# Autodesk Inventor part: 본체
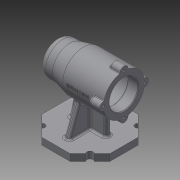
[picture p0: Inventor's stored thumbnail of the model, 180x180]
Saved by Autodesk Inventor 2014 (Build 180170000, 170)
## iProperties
Created: 2021-01
Part Number: 본체
Material: Generic
Document SubType Name: Modeling
Designer: kh
Density: 1 g/cm^3
Appearance: Default
Author: kh
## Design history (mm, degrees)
sketch "Sketch1" dims "d0" = 100
  geometry: L1 (20.711, 50)-(50, 20.711); L2 (50, 20.711)-(50, -20.711); L3 (50, -20.711)-(20.711, -50); L4 (20.711, -50)-(-20.711, -50); L5 (-20.711, -50)-(-50, -20.711); L6 (-50, -20.711)-(-50, 20.711); L7 (-50, 20.711)-(-20.711, 50); L8 (-20.711, 50)-(20.711, 50); L9 (0, 0)-(0, 50); 4 further points
  constraints: 18 end point, 3 coincident, 1 midpoint, 1 vertical, 20 other
  dimensions: "d12" = 50 distance of L9.start L9.end
extrude "Extrusion1" new body sketch "Sketch1" distance "d1" = 10; taper "d2" = 0 deg
workplane "Work Plane1"
sketch "Sketch2"
  geometry: L1 (-19.134, 0)-(19.134, 0) reference; L2 (-19.134, 0)-(-19.134, 10) reference; L3 (19.134, 10)-(-19.134, 10) reference; L4 (19.134, 0)-(19.134, 10) reference; L5 (-46.194, 0)-(-19.134, 0) reference; L6 (-46.194, 0)-(-46.194, 10) reference; L7 (-19.134, 10)-(-46.194, 10) reference; L8 (-19.134, 0)-(-19.134, 10) reference; L9 (19.134, 0)-(46.194, 0) reference; L10 (19.134, 0)-(19.134, 10) reference; L11 (46.194, 10)-(19.134, 10) reference; L12 (46.194, 0)-(46.194, 10) reference; L13 (-50, 75)-(-30, 75); L14 (-30, 75)-(-30, 100); L15 (-30, 100)-(-50, 100); L16 (-50, 100)-(-50, 75); L17 (-30, 75)-(-10, 75); L18 (-10, 75)-(-10, 105); L19 (-30, 100)-(-30, 75); L20 (-10, 75)-(50, 75); L21 (50, 75)-(50, 105); L22 (50, 105)-(-10, 105); L23 (-10, 105)-(-10, 75); L24 (-30, 100)-(-10, 105); L25 (-50, 0)-(-20.711, 0) reference; L26 (-50, 0)-(-50, 10) reference; L27 (-20.711, 10)-(-50, 10) reference; L28 (-20.711, 0)-(-20.711, 10) reference; L29 (-20.711, 0)-(20.711, 0) reference; L30 (-20.711, 0)-(-20.711, 10) reference; L31 (20.711, 10)-(-20.711, 10) reference; L32 (20.711, 0)-(20.711, 10) reference; L33 (20.711, 0)-(50, 0) reference; L34 (20.711, 0)-(20.711, 10) reference; L35 (50, 10)-(20.711, 10) reference; L36 (50, 0)-(50, 10) reference
  constraints: 24 end point, 5 parallel, 3 horizontal, 3 perpendicular, 1 collinear
  dimensions: "d5" = 50 diameter of L15 L13; "d7" = 60 diameter of L22 L20; "d8" = 100 distance between parallel lines of L21 L16; "d9" = 40 distance between parallel lines of L16 L18; "d10" = 20 distance between parallel lines of L16 L14; "d14" = 75 distance of L13.start L25.start
revolve "Revolution2" sketch "Sketch2" stored, may be unused: angle "d15" = 90 deg
workplane "Work Plane2"
sketch "Sketch3"
  geometry: L1 (-50, 50)-(-50, 100) reference; L2 (50, 45)-(50, 105) reference; L3 (-50, 75)-(50, 75); L4 (50, 75)-(35, 75); L5 (35, 75)-(35, 96); L6 (35, 96)-(50, 96); L7 (50, 96)-(50, 75); L8 (35, 75)-(-7, 75); L9 (-7, 75)-(-7, 99); L10 (-7, 99)-(35, 99); L11 (35, 99)-(35, 75); L12 (-7, 75)-(-19, 75); L13 (-19, 75)-(-19, 96); L14 (-19, 96)-(-7, 96); L15 (-7, 96)-(-7, 75); L16 (-19, 75)-(-37, 75); L17 (-37, 75)-(-37, 92.5); L18 (-37, 92.5)-(-19, 92.5); L19 (-19, 92.5)-(-19, 75); L20 (-37, 75)-(-41, 75); L21 (-41, 75)-(-41, 91); L22 (-41, 91)-(-37, 91); L23 (-37, 91)-(-37, 75); L24 (-41, 75)-(-44, 75); L25 (-44, 75)-(-44, 85.5); L26 (-44, 85.5)-(-41, 85.5); L27 (-41, 85.5)-(-41, 75); 1 further point
  constraints: 50 end point, 12 parallel, 6 horizontal, 6 perpendicular, 2 midpoint
  dimensions: "d17" = 15 distance between parallel lines of L5 L7; "d18" = 42 distance between parallel lines of L15 L5; "d19" = 12 distance between parallel lines of L13 L15; "d20" = 18 distance between parallel lines of L17 L13; "d21" = 4 distance between parallel lines of L17 L21; "d22" = 3 distance between parallel lines of L21 L25; "d23" = 42 diameter of L6 L3; "d24" = 48 diameter of L10 L3; "d25" = 42 diameter of L14 L12; "d26" = 35 diameter of L18 L16; "d27" = 32 diameter of L22 L3; "d28" = 21 diameter of L26 L24
revolve "Revolution3" sketch "Sketch3" stored, may be unused: angle "d29" = 90 deg
fillet "Fillet1" dims "d30" = 0.3
fillet "Fillet2" dims "d31" = 3
fillet "Fillet3" dims "d32" = 3
chamfer "Chamfer1" distance "d33" = 1; stored, may be unused: second distance "d34" = 2, angle "d35" = 45 deg
sketch "Sketch4" dims "d36" = 60
  geometry: L1 (0, 0)-(0, -34.728); C1 r 25 at (0, 0) reference; C2 r 30 at (0, 0) reference; C3 r 6 at (0, -30); 2 further points
  constraints: 2 coincident, 2 end point, 1 centre point, 1 point on line, 1 vertical, 1 vertical alignment, 2 other
  dimensions: "d37" = 12 diameter of C3
extrude "Extrusion2" join sketch "Sketch4" distance "d38" = 16; taper "d39" = 0 deg
pattern_circular "Circular Pattern1" dims angle "d41" = 360 deg
sketch "Sketch5"
  geometry: C1 r 22 at (0, 30) reference; A1 r 30 centre (0, 30) between (-29.4, 24.03) and (-5.97, 0.6) reference; A2 r 6 centre (0, 0) between (-5.97, 0.6) and (5.97, 0.6) reference; A3 r 30 centre (0, 30) between (5.97, 0.6) and (29.4, 24.03) reference; A4 r 6 centre (30, 30) between (29.4, 24.03) and (29.4, 35.97) reference; A5 r 30 centre (0, 30) between (29.4, 35.97) and (5.97, 59.4) reference; A6 r 6 centre (0, 60) between (5.97, 59.4) and (-5.97, 59.4) reference; A7 r 30 centre (0, 30) between (-5.97, 59.4) and (-29.4, 35.97) reference; A8 r 6 centre (-30, 30) between (-29.4, 35.97) and (-29.4, 24.03) reference; 5 further points
  constraints: 4 coincident
hole "Hole1" sketch "Sketch5" at (0, 0), (30, 30), (0, 60), (-30, 30) diameter "d43" = 3.242; stored, may be unused: countersink angle "d47" = 90 deg, drill point angle "d49" = 118 deg; dims "d44" = 8, "d45" = 4, "d46" = 2, "d48" = 10
sketch "Sketch6"
  geometry: L1 (20.711, 50)-(50, 20.711) reference; L2 (50, 20.711)-(50, -20.711) reference; L3 (50, -20.711)-(20.711, -50) reference; L4 (20.711, -50)-(-20.711, -50) reference; L5 (-20.711, -50)-(-50, -20.711) reference; L6 (-50, -20.711)-(-50, 20.711) reference; L7 (-50, 20.711)-(-20.711, 50) reference; L8 (-20.711, 50)-(20.711, 50) reference; L9 (0, 0)-(-35.355, -35.355); L10 (0, 0)-(-50, 0); L11 (0, 0)-(-35.355, 35.355); L12 (0, 0)-(35.355, -35.355); L13 (0, 0)-(35.355, 35.355); A1 r 50 centre (0, 0) between (-35.355, -35.355) and (-50, 0); 5 further points
  constraints: 10 end point, 5 coincident, 5 midpoint, 5 point on circle, 1 centre point
  dimensions: "d50" = 100 diameter of A1
hole "Hole2" sketch "Sketch6" at (-35.355, -35.355), (-35.355, 35.355), (35.355, 35.355), (35.355, -35.355) diameter "d51" = 9; stored, may be unused: countersink angle "d55" = 90 deg, drill point angle "d57" = 118 deg; dims "d52" = 8, "d53" = 4, "d54" = 2, "d56" = 10
sketch "Sketch7"
  geometry: L1 (38.537, 32.173)-(50, 20.711) reference; L2 (50, 20.711)-(50, -20.711) reference; L3 (50, -20.711)-(38.537, -32.173) reference; L4 (32.173, -38.537)-(20.711, -50) reference; L5 (20.711, -50)-(-20.711, -50) reference; L6 (-20.711, -50)-(-32.173, -38.537) reference; L7 (-38.537, -32.173)-(-50, -20.711) reference; L8 (-50, -20.711)-(-50, 20.711) reference; L9 (-50, 20.711)-(-38.537, 32.173) reference; L10 (-32.173, 38.537)-(-20.711, 50) reference; L11 (-20.711, 50)-(20.711, 50) reference; L12 (20.711, 50)-(32.173, 38.537) reference; L13 (4, -4)-(-4, -4); L14 (-4, -4)-(-4, 4); L15 (-4, 4)-(4, 4); L16 (4, 4)-(4, -4); L17 (4, -4)-(-4, 4); L18 (-4, -4)-(4, 4); L19 (4, 4)-(-4, 4); L20 (-4, 4)-(-4, 27); L21 (-4, 27)-(4, 27); L22 (4, 27)-(4, 4); A1 r 4.5 centre (35.355, 35.355) between (32.173, 38.537) and (38.537, 32.173) reference; A2 r 4.5 centre (35.355, -35.355) between (38.537, -32.173) and (32.173, -38.537) reference; A3 r 4.5 centre (-35.355, -35.355) between (-32.173, -38.537) and (-38.537, -32.173) reference; A4 r 4.5 centre (-35.355, 35.355) between (-38.537, 32.173) and (-32.173, 38.537) reference; 1 further point
  constraints: 20 end point, 4 parallel, 2 horizontal, 2 midpoint, 2 perpendicular, 1 collinear
  dimensions: "d58" = 8 distance of L13.end L14.end; "d59" = 8 distance of L14.end L15.end; "d89" = 23 distance between parallel lines of L21 L11
  node "Projected Loop10"
extrude "Extrusion3" join sketch "Sketch7" stored distance "d60" = 16; taper "d61" = 0 deg
workplane "Work Plane3"
sketch "Sketch8"
  geometry: L1 (-50, 0)-(-50, 10) reference; L2 (-38.537, 10)-(-50, 10) reference; L3 (50, 10)-(38.537, 10) reference; L4 (50, 0)-(50, 10) reference; L5 (-35, 10)-(-22.074, 45.513); L6 (35, 10)-(22.341, 44.781); 1 further point
  constraints: 4 end point, 2 point on line
  dimensions: "d64" = 110 deg angle of L2 L5; "d65" = 15 distance from line of L5.start L1; "d66" = 110 deg angle of L6 L3; "d67" = 15 distance of L6.start L3.start
feature "Rib1" dims "d68" = 1, "d69" = 8, "d70" = 0, "d71" = 0, "d72" = 1, "d73" = 1
feature "Rib2" dims "d74" = 1, "d75" = 8, "d76" = 0, "d77" = 0, "d78" = 1, "d79" = 1
workplane "Work Plane4"
sketch "Sketch9"
  geometry: L1 (-38.537, 10)-(-50, 10) reference; L2 (-38.537, 10)-(-30.855, 10) reference; L3 (-20.711, 10)-(-32.173, 10) reference; L4 (-50, 0)-(-50, 10) reference; L5 (-27, 10)-(-20.559, 43.137); 1 further point
  constraints: 2 end point, 1 point on line
  dimensions: "d81" = 101 deg angle of L5 L1; "d82" = 23 distance from line of L5.start L4
feature "Rib3" sketch "Sketch9" dims "d83" = 1, "d84" = 8, "d85" = 0, "d86" = 0, "d87" = 1, "d88" = 1
extrude "Extrusion4" join sketch "Sketch7" stored distance "d90" = 16; taper "d91" = 0 deg
fillet "Fillet4" dims "d92" = 10
fillet "Fillet5" dims "d93" = 3
fillet "Fillet6" dims "d94" = 1
fillet "Fillet7" dims "d95" = 3
fillet "Fillet8" dims "d96" = 3
fillet "Fillet9" dims "d97" = 3
workplane "Work Plane5"
sketch "Sketch11"
  geometry: L1 (-24.592, 2.402)-(8.592, 2.402); L2 (8.592, 2.402)-(8.592, -2.402); L3 (8.592, -2.402)-(-24.592, -2.402); L4 (-24.592, -2.402)-(-24.592, 2.402); L5 (-24.592, 0)-(8.592, 0); L6 (-8, 2.402)-(-8, -2.402); L7 (30, 6.771)-(30, 29.226) reference; L8 (-70, -15)-(-70, 15) reference; L9 (-70, 0)-(30, 0); 1 further point
  constraints: 6 end point, 5 midpoint, 1 collinear, 1 perpendicular, 2 other
  dimensions: "d98" = 38 distance between parallel lines of L7 L6
emboss "Emboss1" sketch "Sketch11" dims "d5" = 50, "d7" = 60, "d8" = 100, "d9" = 40, "d10" = 20, "d14" = 75, "d99" = 0.5, "d100" = 0
fillet "Fillet10" dims "d101" = 3
body "Solid1"
node "Projected Loop1"
node "Projected Loop2"
node "Projected Loop3"
node "Projected Loop4"
node "Projected Loop5"
node "Projected Loop6"
node "Projected Loop7"
node "Projected Loop8"
node "Projected Loop9"
other parameters: "d3" = 0, "d16" = 0, "d62" = 0, "d80" = 0
